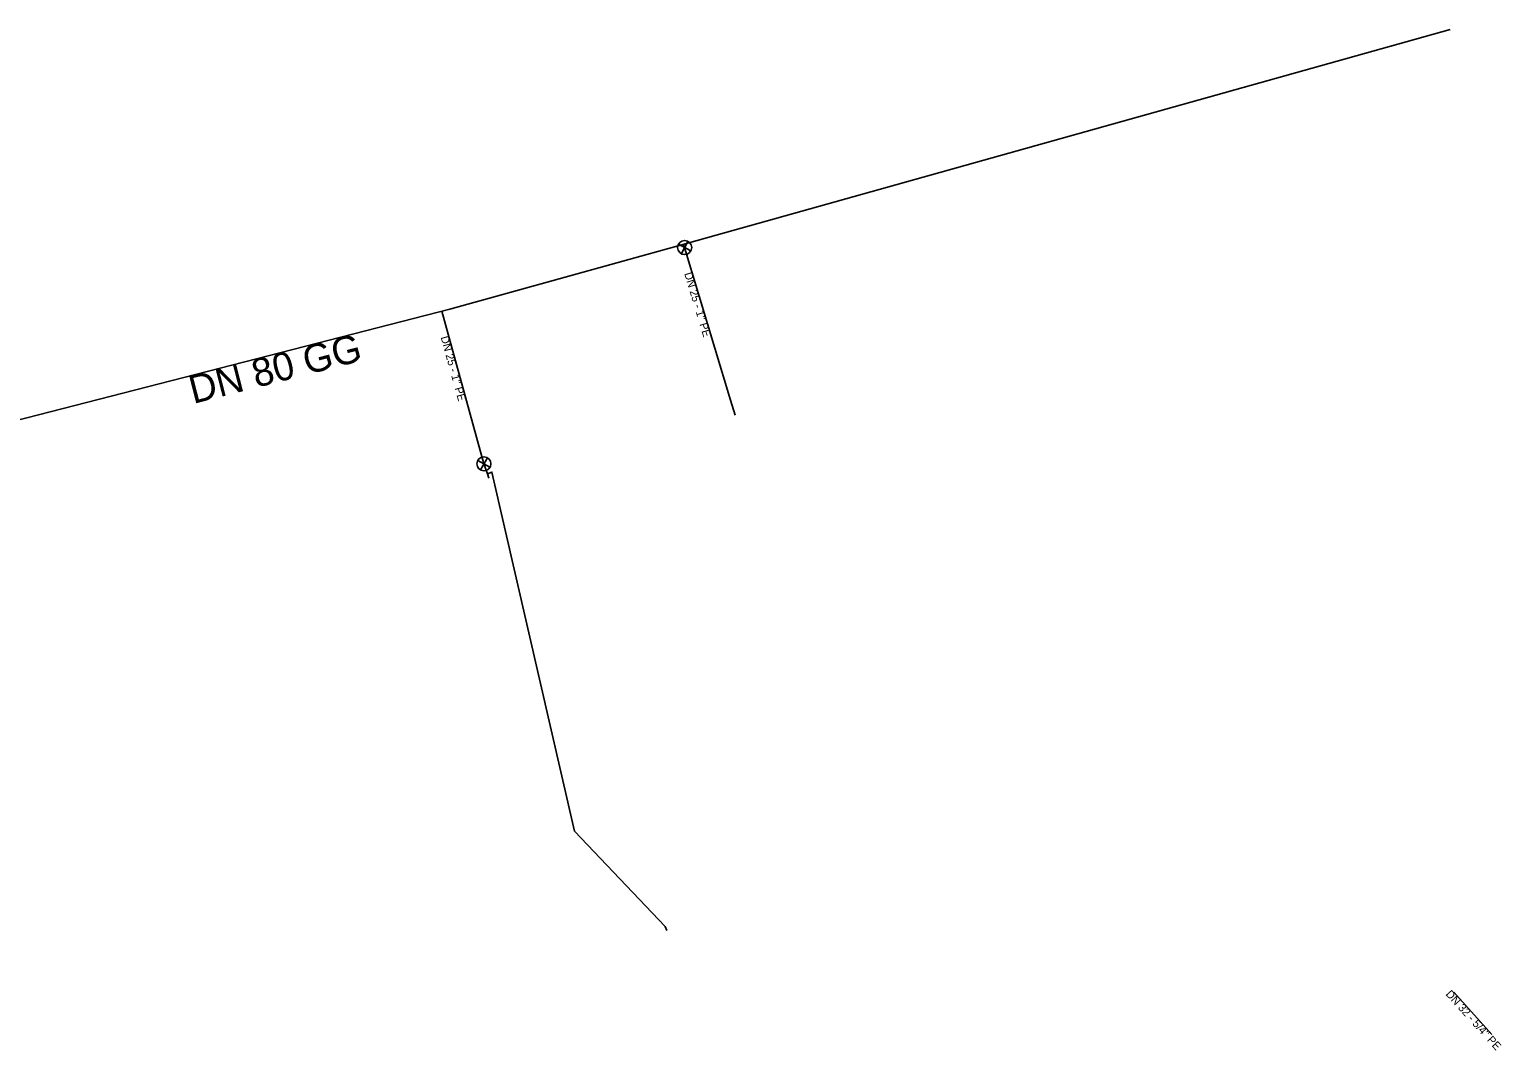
# Model space of a CAD drawing. Extents: x -446989 to -446811, y -1113341 to -1113211.
# Drawn here: x -446894.4 to -446810.6, y -1113269.6 to -1113211.5 of the extents above; entities that cross this region are included whole.
import ezdxf

# ---------------------------------------------------------------- set-up
doc = ezdxf.new("R2010")
doc.units = 0
for name, color, linetype in [('_pripojka_priblizne_', 7, 'Continuous'), ('_voda_smvak_prevzato_z_dokumentace_', 7, 'Continuous'), ('Default', 7, 'Continuous'), ('MoLevel 32', 7, 'Continuous'), ('MoLevel 46', 7, 'Continuous'), ('MoLevel 53', 7, 'Continuous')]:
    doc.layers.add(name, color=color, linetype=linetype)

# ---------------------------------------------------------------- blocks, each defined once
blk = doc.blocks.new('_uzaver_pripojka_')
at = {"layer": 'Default'}
for p, q in [((-0.000035, -0.000035), (0.000035, 0.000035)), ((0.000035, -0.000035), (-0.000035, 0.000035))]:
    blk.add_line(p, q, dxfattribs=at)
for radius in [0.00005, 0.0000025]:
    blk.add_circle((0, 0), radius, dxfattribs=at)

msp = doc.modelspace()

# ---------------------------------------------------------------- linework, layer by layer
at = {"layer": '_pripojka_priblizne_'}
for p, q in [((-446868.31, -1113236.772), (-446868.222, -1113237.018)), ((-446811.182, -1113268.676), (-446813.347, -1113266.275))]:
    msp.add_line(p, q, dxfattribs=at)
for points in [[(-446857.151, -1113223.71), (-446854.477, -1113232.582), (-446854.217, -1113233.445)], [(-446870.898, -1113227.515), (-446868.51, -1113236.21), (-446868.31, -1113236.772)], [(-446868.31, -1113236.772), (-446868.051, -1113236.684), (-446863.352, -1113257.119), (-446858.201, -1113262.529), (-446858.113, -1113262.761)]]:
    msp.add_lwpolyline(points, dxfattribs=at)
at = {"layer": '_voda_smvak_prevzato_z_dokumentace_'}
msp.add_lwpolyline([(-446945.52, -1113246.69), (-446870.45, -1113227.4), (-446857.33, -1113223.76), (-446813.55, -1113211.49)], dxfattribs=at)

# ---------------------------------------------------------------- block references
at = {"layer": 'MoLevel 53', "xscale": 7999.999999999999, "yscale": 7999.999999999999}
for p, rotation in [((-446857.093, -1113223.901), -73.22799237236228), ((-446868.51, -1113236.21), 105.55448983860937)]:
    msp.add_blockref('_uzaver_pripojka_', p, dxfattribs=dict(at, rotation=rotation))

# ---------------------------------------------------------------- texts
at = {"layer": 'MoLevel 32'}
for s, rotation, p in [("DN 25 - 1'' PE", 286.77201, (-446857.122, -1113225.383)), ("DN 25 - 1'' PE", 285.36023, (-446870.974, -1113229.004)), ("DN 32 - 5/4'' PE", 312.0461, (-446813.841, -1113266.407))]:
    msp.add_text(s, height=0.455, rotation=rotation, dxfattribs=at).set_placement(p)
at = {"layer": 'MoLevel 46'}
msp.add_text('DN 80 GG', height=1.6049, rotation=14.41095, dxfattribs=at).set_placement((-446885.044, -1113232.807))

doc.saveas('drawing.dxf')
